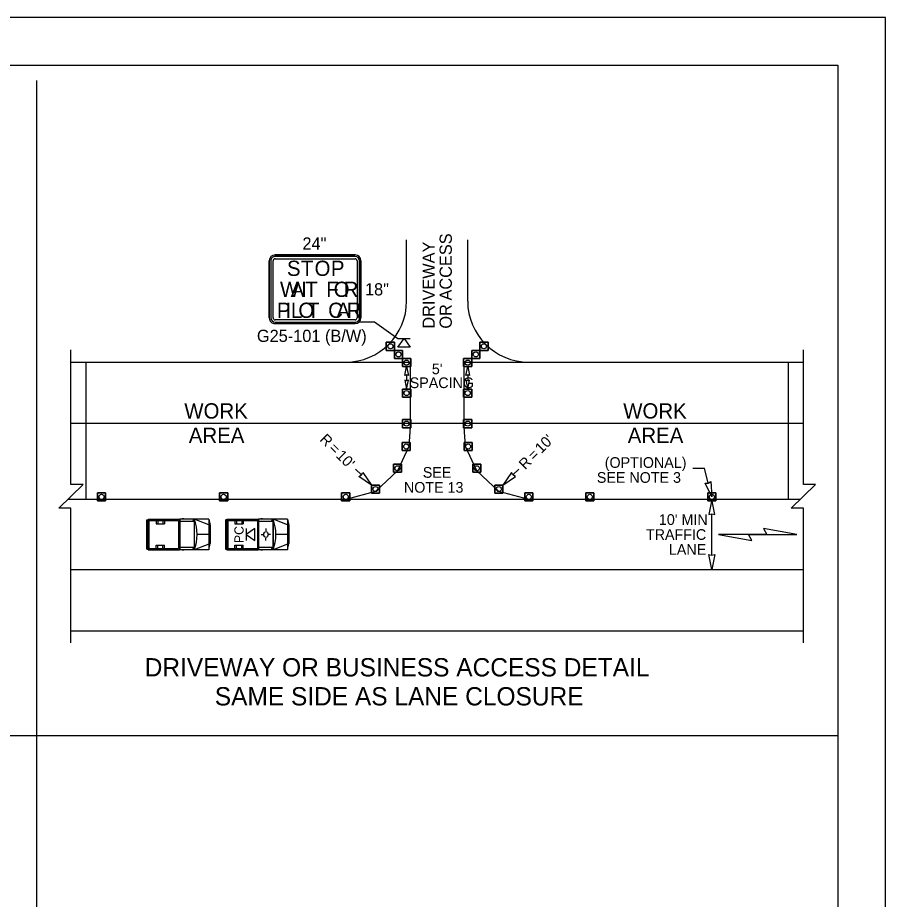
# Model space of a CAD drawing. Extents: x 99999.1 to 100095.7, y 99995 to 100010.7.
# Drawn here: x 100030.38 to 100036.06, y 100004.91 to 100010.69 of the extents above; entities that cross this region are included whole.
import ezdxf

# ---------------------------------------------------------------- set-up
doc = ezdxf.new("R2010")
doc.units = 0
for name, color, linetype in [('RD_ED_DrivewayEdge', 7, 'Continuous'), ('RD_ED_ShoulderPavedEdge', 7, 'Continuous'), ('RD_MK_LineEdgeWhite', 7, 'Continuous'), ('RD_MK_LineSkipCenter', 7, 'Continuous'), ('SH_DE_DetailHeading2Text', 7, 'Continuous'), ('SH_GI_PlotLimits', 7, 'Continuous'), ('SH_GI_SheetBorder', 7, 'Continuous'), ('TR_SN_ConstructionSigns', 7, 'Continuous'), ('TR_WZ_MotoristVehicle', 7, 'Continuous'), ('TR_WZ_PortableSignMountBlk-Wht', 7, 'Continuous'), ('TR_WZ_TrafficCone', 7, 'Continuous'), ('TR_WZ_WorkAreaLabel', 7, 'Continuous'), ('TR_WZ_WorkZoneDetails', 7, 'Continuous'), ('TR_WZ_WorkZoneTextCurrent', 7, 'Continuous')]:
    doc.layers.add(name, color=color, linetype=linetype)

msp = doc.modelspace()

# ---------------------------------------------------------------- linework, layer by layer
at = {"layer": 'RD_ED_DrivewayEdge'}
for p, q in [((100032.925, 100008.8304), (100032.925, 100009.2305)), ((100033.325, 100008.8304), (100033.325, 100009.2305))]:
    msp.add_line(p, q, dxfattribs=at)
for centre, start, end in [((100032.525, 100008.8304), 270, 0), ((100033.725, 100008.8304), 180, 270)]:
    msp.add_arc(centre, 0.4, start, end, dxfattribs=at)
at = {"layer": 'RD_ED_ShoulderPavedEdge'}
for p, q in [((100030.725, 100008.4305), (100032.525, 100008.4305)), ((100033.725, 100008.4305), (100035.525, 100008.4305)), ((100030.725, 100006.6704), (100035.525, 100006.6704))]:
    msp.add_line(p, q, dxfattribs=at)
at = {"layer": 'RD_MK_LineEdgeWhite'}
for p, q in [((100030.725, 100008.0305), (100035.525, 100008.0305)), ((100030.725, 100007.0704), (100035.525, 100007.0704))]:
    msp.add_line(p, q, dxfattribs=at)
at = {"layer": 'RD_MK_LineSkipCenter'}
msp.add_lwpolyline([(100035.5043, 100007.5305), (100030.7043, 100007.5305)], dxfattribs=at)
at = {"layer": 'SH_GI_PlotLimits'}
msp.add_lwpolyline([(100019.0625, 99999.6875), (100036.0625, 99999.6875), (100036.0625, 100010.6875), (100019.0625, 100010.6875)], close=True, dxfattribs=at)
at = {"layer": 'SH_GI_SheetBorder'}
for p, q in [((100020, 100010.375), (100035.75, 100010.375)), ((100035.75, 100010.375), (100035.75, 100000))]:
    msp.add_line(p, q, dxfattribs=at)
at = {"layer": 'TR_SN_ConstructionSigns'}
for p, q in [((100032.025, 100008.7198), (100032.025, 100009.0948)), ((100032.025, 100009.0948), (100032.025, 100008.7198)), ((100032.025, 100009.0948), (100032.025, 100008.7198)), ((100032.0344, 100009.0948), (100032.0344, 100008.7198)), ((100032.05, 100008.7198), (100032.05, 100009.0948)), ((100032.0625, 100009.1323), (100032.5875, 100009.1323)), ((100032.5875, 100009.1323), (100032.0625, 100009.1323)), ((100032.5875, 100009.1323), (100032.0625, 100009.1323)), ((100032.5875, 100009.1229), (100032.0625, 100009.1229)), ((100032.0625, 100009.1073), (100032.5875, 100009.1073)), ((100032.6, 100009.0948), (100032.6, 100008.7198)), ((100032.6156, 100008.7198), (100032.6156, 100009.0948)), ((100032.625, 100009.0948), (100032.625, 100008.7198)), ((100032.625, 100008.7198), (100032.625, 100009.0948)), ((100032.625, 100008.7198), (100032.625, 100009.0948)), ((100032.5875, 100008.7073), (100032.0625, 100008.7073)), ((100032.0625, 100008.6916), (100032.5875, 100008.6916)), ((100032.5875, 100008.6823), (100032.0625, 100008.6823)), ((100032.0625, 100008.6823), (100032.5875, 100008.6823)), ((100032.0625, 100008.6823), (100032.5875, 100008.6823))]:
    msp.add_line(p, q, dxfattribs=at)
for centre, radius, start, end in [((100032.0625, 100009.0948), 0.0375, 90, 180), ((100032.0625, 100009.0948), 0.0375, 90, 180), ((100032.0625, 100009.0948), 0.0375, 90, 180), ((100032.0625, 100009.0948), 0.0281, 90, 180.00001), ((100032.0625, 100009.0948), 0.0125, 90, 180.00001), ((100032.5875, 100009.0948), 0.0375, 0, 90), ((100032.5875, 100009.0948), 0.0375, 0, 90), ((100032.5875, 100009.0948), 0.0375, 0, 90), ((100032.5875, 100009.0948), 0.0281, 0, 90), ((100032.5875, 100009.0948), 0.0125, 0, 90), ((100032.0625, 100008.7198), 0.0375, 180, 270.00001), ((100032.0625, 100008.7198), 0.0375, 180, 270.00001), ((100032.0625, 100008.7198), 0.0375, 180, 270.00001), ((100032.0625, 100008.7198), 0.0281, 180.00001, 270), ((100032.0625, 100008.7198), 0.0125, 180.00001, 270), ((100032.5875, 100008.7198), 0.0375, 270.00001, 0.00001), ((100032.5875, 100008.7198), 0.0375, 270.00001, 0.00001), ((100032.5875, 100008.7198), 0.0281, 270, 0.00001), ((100032.5875, 100008.7198), 0.0125, 270, 0.00001), ((100032.5875, 100008.7198), 0.0375, 270.00001, 0.00001)]:
    msp.add_arc(centre, radius, start, end, dxfattribs=at)
at = {"layer": 'TR_WZ_MotoristVehicle'}
for p, q in [((100031.2207, 100007.3911), (100031.2207, 100007.2098)), ((100031.2252, 100007.3972), (100031.2297, 100007.3972)), ((100031.2297, 100007.3972), (100031.2297, 100007.2037)), ((100031.2304, 100007.4005), (100031.4361, 100007.4005)), ((100031.2304, 100007.4005), (100031.2304, 100007.2005)), ((100031.2362, 100007.3925), (100031.2362, 100007.2084)), ((100031.2362, 100007.3925), (100031.4302, 100007.3925)), ((100031.2826, 100007.3925), (100031.2826, 100007.3695)), ((100031.2826, 100007.3695), (100031.3375, 100007.3695)), ((100031.2936, 100007.3925), (100031.2936, 100007.3695)), ((100031.3276, 100007.3925), (100031.3276, 100007.3695)), ((100031.3375, 100007.3925), (100031.3375, 100007.3695)), ((100031.4302, 100007.3925), (100031.4302, 100007.2084)), ((100031.4361, 100007.4005), (100031.4361, 100007.2005)), ((100031.4388, 100007.4005), (100031.4388, 100007.2005)), ((100031.6277, 100007.4005), (100031.4388, 100007.4005)), ((100031.5316, 100007.385), (100031.4388, 100007.385)), ((100031.4646, 100007.4033), (100031.4533, 100007.4033)), ((100031.5316, 100007.4005), (100031.5195, 100007.385)), ((100031.5316, 100007.4005), (100031.5316, 100007.2005)), ((100031.5333, 100007.4005), (100031.5333, 100007.2005)), ((100031.6277, 100007.3638), (100031.5333, 100007.4005)), ((100031.6277, 100007.4005), (100031.6277, 100007.2005)), ((100031.6277, 100007.4005), (100031.637, 100007.3601)), ((100031.637, 100007.3601), (100031.637, 100007.2408)), ((100031.737, 100007.3911), (100031.737, 100007.2098)), ((100031.7415, 100007.3972), (100031.7459, 100007.3972)), ((100031.7459, 100007.3972), (100031.7459, 100007.2037)), ((100031.7466, 100007.4005), (100031.9523, 100007.4005)), ((100031.7466, 100007.4005), (100031.7466, 100007.2005)), ((100031.7525, 100007.3925), (100031.7525, 100007.2084)), ((100031.7525, 100007.3925), (100031.9465, 100007.3925)), ((100031.7988, 100007.3925), (100031.7988, 100007.3695)), ((100031.7988, 100007.3695), (100031.8538, 100007.3695)), ((100031.8098, 100007.3925), (100031.8098, 100007.3695)), ((100031.8438, 100007.3925), (100031.8438, 100007.3695)), ((100031.8538, 100007.3925), (100031.8538, 100007.3695)), ((100031.9465, 100007.3925), (100031.9465, 100007.2084)), ((100031.9523, 100007.4005), (100031.9523, 100007.2005)), ((100031.9551, 100007.4005), (100031.9551, 100007.2005)), ((100032.144, 100007.4005), (100031.9551, 100007.4005)), ((100032.0478, 100007.385), (100031.9551, 100007.385)), ((100031.9809, 100007.4033), (100031.9695, 100007.4033)), ((100032.0478, 100007.4005), (100032.0358, 100007.385)), ((100032.0478, 100007.4005), (100032.0478, 100007.2005)), ((100032.0495, 100007.4005), (100032.0495, 100007.2005)), ((100032.144, 100007.3638), (100032.0495, 100007.4005)), ((100032.144, 100007.4005), (100032.144, 100007.2005)), ((100032.144, 100007.4005), (100032.1533, 100007.3601)), ((100032.1533, 100007.3601), (100032.1533, 100007.2408)), ((100031.2207, 100007.3145), (100031.2297, 100007.3108)), ((100031.2207, 100007.2864), (100031.2297, 100007.2901)), ((100031.2231, 100007.3005), (100031.2273, 100007.3005)), ((100031.2252, 100007.3033), (100031.2252, 100007.2976)), ((100031.6277, 100007.3005), (100031.5518, 100007.3005)), ((100031.737, 100007.3145), (100031.7459, 100007.3108)), ((100031.737, 100007.2864), (100031.7459, 100007.2901)), ((100031.7394, 100007.3005), (100031.7435, 100007.3005)), ((100031.7415, 100007.3033), (100031.7415, 100007.2976)), ((100031.9716, 100007.2997), (100031.9865, 100007.3001)), ((100031.9884, 100007.3001), (100031.9884, 100007.3001)), ((100032.0025, 100007.3401), (100032.0025, 100007.3239)), ((100032.0326, 100007.3006), (100032.02, 100007.3005)), ((100032.144, 100007.3005), (100032.0681, 100007.3005)), ((100031.6277, 100007.2371), (100031.5333, 100007.2005)), ((100031.6277, 100007.2005), (100031.637, 100007.2408)), ((100032.0018, 100007.262), (100032.0021, 100007.277)), ((100032.144, 100007.2371), (100032.0495, 100007.2005)), ((100032.144, 100007.2005), (100032.1533, 100007.2408)), ((100031.2252, 100007.2037), (100031.2297, 100007.2037)), ((100031.2304, 100007.2005), (100031.4361, 100007.2005)), ((100031.2362, 100007.2084), (100031.4302, 100007.2084)), ((100031.2826, 100007.2084), (100031.2826, 100007.2314)), ((100031.2826, 100007.2314), (100031.3375, 100007.2314)), ((100031.2936, 100007.2084), (100031.2936, 100007.2314)), ((100031.3276, 100007.2084), (100031.3276, 100007.2314)), ((100031.3375, 100007.2084), (100031.3375, 100007.2314)), ((100031.5316, 100007.216), (100031.4388, 100007.216)), ((100031.6277, 100007.2005), (100031.4388, 100007.2005)), ((100031.4646, 100007.1976), (100031.4533, 100007.1976)), ((100031.5216, 100007.216), (100031.5316, 100007.2005)), ((100031.7415, 100007.2037), (100031.7459, 100007.2037)), ((100031.7466, 100007.2005), (100031.9523, 100007.2005)), ((100031.7525, 100007.2084), (100031.9465, 100007.2084)), ((100031.7988, 100007.2084), (100031.7988, 100007.2314)), ((100031.7988, 100007.2314), (100031.8538, 100007.2314)), ((100031.8098, 100007.2084), (100031.8098, 100007.2314)), ((100031.8438, 100007.2084), (100031.8438, 100007.2314)), ((100031.8538, 100007.2084), (100031.8538, 100007.2314)), ((100032.0478, 100007.216), (100031.9551, 100007.216)), ((100032.144, 100007.2005), (100031.9551, 100007.2005)), ((100031.9809, 100007.1976), (100031.9695, 100007.1976)), ((100032.0379, 100007.216), (100032.0478, 100007.2005))]:
    msp.add_line(p, q, dxfattribs=at)
for centre, major_axis, start_param, end_param in [((100031.2252, 100007.3911), (0, 0.0061), 6.283185, 7.853982), ((100031.3983, 100007.3004), (0, 0.2099), 4.215852, 5.209111), ((100031.7415, 100007.3911), (0, 0.0061), 6.283185, 7.853982), ((100031.9146, 100007.3004), (0, 0.2099), 4.215852, 5.209111), ((100031.2252, 100007.2098), (0, -0.0061), 4.712389, 6.283185), ((100031.7415, 100007.2098), (0, -0.0061), 4.712389, 6.283185)]:
    msp.add_ellipse(centre, major_axis=major_axis, ratio=0.73155, start_param=start_param, end_param=end_param, dxfattribs=at)
for centre, major_axis in [((100031.2252, 100007.3005), (0, -0.00282)), ((100031.7415, 100007.3005), (0, -0.00282)), ((100032.0025, 100007.3005), (0, -0.0193))]:
    msp.add_ellipse(centre, major_axis=major_axis, ratio=0.73155, dxfattribs=at)
at = {"layer": 'TR_WZ_PortableSignMountBlk-Wht'}
for p, q in [((100032.8683, 100008.5846), (100032.9483, 100008.5846)), ((100031.8727, 100007.3404), (100031.8727, 100007.2604))]:
    msp.add_line(p, q, dxfattribs=at)
for points in [[(100032.9083, 100008.5846), (100032.9483, 100008.5271), (100032.8683, 100008.5271)], [(100031.8727, 100007.3004), (100031.9301, 100007.2604), (100031.9301, 100007.3404)]]:
    msp.add_lwpolyline(points, close=True, dxfattribs=at)
at = {"layer": 'TR_WZ_TrafficCone'}
for points in [[(100032.7917, 100008.5605), (100032.845, 100008.5605), (100032.845, 100008.5071), (100032.7917, 100008.5071), (100032.7917, 100008.5605)], [(100032.7917, 100008.5071), (100032.845, 100008.5071), (100032.845, 100008.5605), (100032.7917, 100008.5605), (100032.7917, 100008.5071)], [(100033.405, 100008.5605), (100033.4583, 100008.5605), (100033.4583, 100008.5071), (100033.405, 100008.5071), (100033.405, 100008.5605)], [(100033.405, 100008.5071), (100033.4583, 100008.5071), (100033.4583, 100008.5605), (100033.405, 100008.5605), (100033.405, 100008.5071)], [(100032.845, 100008.5071), (100032.8984, 100008.5071), (100032.8984, 100008.4538), (100032.845, 100008.4538), (100032.845, 100008.5071)], [(100032.845, 100008.4538), (100032.8984, 100008.4538), (100032.8984, 100008.5071), (100032.845, 100008.5071), (100032.845, 100008.4538)], [(100033.3516, 100008.5071), (100033.405, 100008.5071), (100033.405, 100008.4538), (100033.3516, 100008.4538), (100033.3516, 100008.5071)], [(100033.3516, 100008.4538), (100033.405, 100008.4538), (100033.405, 100008.5071), (100033.3516, 100008.5071), (100033.3516, 100008.4538)], [(100032.8984, 100008.4538), (100032.9517, 100008.4538), (100032.9517, 100008.4005), (100032.8984, 100008.4005), (100032.8984, 100008.4538)], [(100032.8984, 100008.4005), (100032.9517, 100008.4005), (100032.9517, 100008.4538), (100032.8984, 100008.4538), (100032.8984, 100008.4005)], [(100033.2983, 100008.4538), (100033.3516, 100008.4538), (100033.3516, 100008.4005), (100033.2983, 100008.4005), (100033.2983, 100008.4538)], [(100033.2983, 100008.4005), (100033.3516, 100008.4005), (100033.3516, 100008.4538), (100033.2983, 100008.4538), (100033.2983, 100008.4005)], [(100032.8984, 100008.2538), (100032.9517, 100008.2538), (100032.9517, 100008.2005), (100032.8984, 100008.2005), (100032.8984, 100008.2538)], [(100032.8984, 100008.2005), (100032.9517, 100008.2005), (100032.9517, 100008.2538), (100032.8984, 100008.2538), (100032.8984, 100008.2005)], [(100033.2983, 100008.2538), (100033.3516, 100008.2538), (100033.3516, 100008.2005), (100033.2983, 100008.2005), (100033.2983, 100008.2538)], [(100033.2983, 100008.2005), (100033.3516, 100008.2005), (100033.3516, 100008.2538), (100033.2983, 100008.2538), (100033.2983, 100008.2005)], [(100032.8984, 100008.0538), (100032.9517, 100008.0538), (100032.9517, 100008.0005), (100032.8984, 100008.0005), (100032.8984, 100008.0538)], [(100032.8984, 100008.0005), (100032.9517, 100008.0005), (100032.9517, 100008.0538), (100032.8984, 100008.0538), (100032.8984, 100008.0005)], [(100033.2983, 100008.0538), (100033.3516, 100008.0538), (100033.3516, 100008.0005), (100033.2983, 100008.0005), (100033.2983, 100008.0538)], [(100033.2983, 100008.0005), (100033.3516, 100008.0005), (100033.3516, 100008.0538), (100033.2983, 100008.0538), (100033.2983, 100008.0005)], [(100032.8956, 100007.9038), (100032.949, 100007.9038), (100032.949, 100007.8505), (100032.8956, 100007.8505), (100032.8956, 100007.9038)], [(100032.8956, 100007.8505), (100032.949, 100007.8505), (100032.949, 100007.9038), (100032.8956, 100007.9038), (100032.8956, 100007.8505)], [(100033.301, 100007.9038), (100033.3544, 100007.9038), (100033.3544, 100007.8505), (100033.301, 100007.8505), (100033.301, 100007.9038)], [(100033.301, 100007.8505), (100033.3544, 100007.8505), (100033.3544, 100007.9038), (100033.301, 100007.9038), (100033.301, 100007.8505)], [(100032.8381, 100007.7615), (100032.8914, 100007.7615), (100032.8914, 100007.7082), (100032.8381, 100007.7082), (100032.8381, 100007.7615)], [(100032.8381, 100007.7082), (100032.8914, 100007.7082), (100032.8914, 100007.7615), (100032.8381, 100007.7615), (100032.8381, 100007.7082)], [(100033.3586, 100007.7615), (100033.4119, 100007.7615), (100033.4119, 100007.7082), (100033.3586, 100007.7082), (100033.3586, 100007.7615)], [(100033.3586, 100007.7082), (100033.4119, 100007.7082), (100033.4119, 100007.7615), (100033.3586, 100007.7615), (100033.3586, 100007.7082)], [(100032.6944, 100007.6247), (100032.7477, 100007.6247), (100032.7477, 100007.5714), (100032.6944, 100007.5714), (100032.6944, 100007.6247)], [(100032.6944, 100007.5714), (100032.7477, 100007.5714), (100032.7477, 100007.6247), (100032.6944, 100007.6247), (100032.6944, 100007.5714)], [(100033.5023, 100007.6247), (100033.5556, 100007.6247), (100033.5556, 100007.5714), (100033.5023, 100007.5714), (100033.5023, 100007.6247)], [(100033.5023, 100007.5714), (100033.5556, 100007.5714), (100033.5556, 100007.6247), (100033.5023, 100007.6247), (100033.5023, 100007.5714)], [(100030.899, 100007.5738), (100030.9524, 100007.5738), (100030.9524, 100007.5205), (100030.899, 100007.5205), (100030.899, 100007.5738)], [(100030.899, 100007.5205), (100030.9524, 100007.5205), (100030.9524, 100007.5738), (100030.899, 100007.5738), (100030.899, 100007.5205)], [(100031.699, 100007.5738), (100031.7524, 100007.5738), (100031.7524, 100007.5205), (100031.699, 100007.5205), (100031.699, 100007.5738)], [(100031.699, 100007.5205), (100031.7524, 100007.5205), (100031.7524, 100007.5738), (100031.699, 100007.5738), (100031.699, 100007.5205)], [(100032.499, 100007.5738), (100032.5524, 100007.5738), (100032.5524, 100007.5205), (100032.499, 100007.5205), (100032.499, 100007.5738)], [(100032.499, 100007.5205), (100032.5524, 100007.5205), (100032.5524, 100007.5738), (100032.499, 100007.5738), (100032.499, 100007.5205)], [(100033.699, 100007.5738), (100033.7524, 100007.5738), (100033.7524, 100007.5205), (100033.699, 100007.5205), (100033.699, 100007.5738)], [(100033.699, 100007.5205), (100033.7524, 100007.5205), (100033.7524, 100007.5738), (100033.699, 100007.5738), (100033.699, 100007.5205)], [(100034.099, 100007.5738), (100034.1524, 100007.5738), (100034.1524, 100007.5205), (100034.099, 100007.5205), (100034.099, 100007.5738)], [(100034.099, 100007.5205), (100034.1524, 100007.5205), (100034.1524, 100007.5738), (100034.099, 100007.5738), (100034.099, 100007.5205)], [(100034.899, 100007.5738), (100034.9524, 100007.5738), (100034.9524, 100007.5205), (100034.899, 100007.5205), (100034.899, 100007.5738)], [(100034.899, 100007.5205), (100034.9524, 100007.5205), (100034.9524, 100007.5738), (100034.899, 100007.5738), (100034.899, 100007.5205)]]:
    msp.add_lwpolyline(points, dxfattribs=at)
for centre in [(100032.8184, 100008.5338), (100033.4316, 100008.5338), (100032.8717, 100008.4805), (100033.3783, 100008.4805), (100032.925, 100008.4271), (100033.325, 100008.4271), (100032.925, 100008.2271), (100033.325, 100008.2271), (100032.925, 100008.0271), (100033.325, 100008.0271), (100032.9223, 100007.8771), (100033.3277, 100007.8771), (100032.8648, 100007.7349), (100033.3852, 100007.7349), (100032.721, 100007.598), (100033.529, 100007.598), (100030.9257, 100007.5471), (100031.7257, 100007.5471), (100032.5257, 100007.5471), (100033.7257, 100007.5471), (100034.1257, 100007.5471), (100034.9257, 100007.5471)]:
    msp.add_circle(centre, 0.0167, dxfattribs=at)
at = {"layer": 'TR_WZ_WorkZoneDetails'}
for p, q in [((100030.5, 100010.275), (100030.5, 100001.6859)), ((100032.614, 100008.6933), (100032.714, 100008.6933)), ((100032.714, 100008.6933), (100032.8683, 100008.5846)), ((100032.9251, 100008.3459), (100032.9251, 100008.3083)), ((100033.325, 100008.3459), (100033.325, 100008.3083)), ((100032.6281, 100007.691), (100032.5897, 100007.7294)), ((100033.6219, 100007.691), (100033.6603, 100007.7294)), ((100034.8007, 100007.7352), (100034.8769, 100007.7352)), ((100034.9022, 100007.6378), (100034.8769, 100007.7352)), ((100034.9256, 100007.1642), (100034.9256, 100007.4367)), ((100035.2856, 100007.3005), (100035.0445, 100007.3005)), ((100035.1651, 100007.3005), (100035.4062, 100007.3005)), ((100030.5, 100005.9804), (100025.25, 100005.9804)), ((100035.75, 100005.9804), (100030.5, 100005.9804))]:
    msp.add_line(p, q, dxfattribs=at)
for points in [[(100030.725, 100006.5904), (100030.725, 100007.473), (100030.645, 100007.473), (100030.805, 100007.6279), (100030.725, 100007.6279), (100030.725, 100008.5105)], [(100035.525, 100006.5904), (100035.525, 100007.473), (100035.445, 100007.473), (100035.605, 100007.6279), (100035.525, 100007.6279), (100035.525, 100008.5105)]]:
    msp.add_lwpolyline(points, dxfattribs=at)
for points in [[(100032.9483, 100008.4305), (100032.9483, 100008.2071), (100032.9483, 100008.0071), (100032.939, 100007.8771), (100032.939, 100007.8771), (100032.939, 100007.8771), (100032.8648, 100007.7182), (100032.8648, 100007.7182), (100032.8648, 100007.7182), (100032.721, 100007.5814), (100032.5257, 100007.5305), (100031.529, 100007.5305), (100030.949, 100007.5305), (100030.825, 100007.5305), (100030.825, 100008.4305)], [(100032.925, 100008.4005), (100032.9363, 100008.3433), (100032.925, 100008.3459), (100032.9138, 100008.3433)], [(100035.425, 100008.4305), (100035.425, 100008.0305), (100035.425, 100007.5305), (100034.501, 100007.5305), (100034.501, 100007.5305), (100034.501, 100007.5305), (100033.7257, 100007.5305), (100033.7257, 100007.5305), (100033.7257, 100007.5305), (100033.529, 100007.5814), (100033.3852, 100007.7182), (100033.311, 100007.8771), (100033.3017, 100008.0071), (100033.3017, 100008.2071), (100033.3017, 100008.4305)], [(100033.325, 100008.4005), (100033.3362, 100008.3433), (100033.325, 100008.3459), (100033.3137, 100008.3433)], [(100032.9251, 100008.2538), (100032.9363, 100008.3109), (100032.9251, 100008.3083), (100032.9139, 100008.3109)], [(100033.325, 100008.2538), (100033.3362, 100008.3109), (100033.325, 100008.3083), (100033.3138, 100008.3109)], [(100032.6944, 100007.6247), (100032.6113, 100007.6806), (100032.6281, 100007.691), (100032.6385, 100007.7079)], [(100033.5556, 100007.6247), (100033.6387, 100007.6806), (100033.6219, 100007.691), (100033.6115, 100007.7079)], [(100034.9257, 100007.5471), (100034.8824, 100007.6374), (100034.9022, 100007.6379), (100034.9197, 100007.6471)], [(100034.9257, 100007.5305), (100034.9064, 100007.4322), (100034.9257, 100007.4367), (100034.945, 100007.4322)], [(100034.9685, 100007.3005), (100035.1873, 100007.2619), (100035.1651, 100007.3005)], [(100035.4821, 100007.3005), (100035.2633, 100007.339), (100035.2856, 100007.3005)], [(100034.9256, 100007.0704), (100034.9064, 100007.1687), (100034.9256, 100007.1642), (100034.9449, 100007.1687)]]:
    msp.add_lwpolyline(points, close=True, dxfattribs=at)

# ---------------------------------------------------------------- texts
at = {"layer": 'SH_DE_DetailHeading2Text'}
for s, p in [('DRIVEWAY OR BUSINESS ACCESS DETAIL', (100031.2082, 100006.3704)), ('SAME SIDE AS LANE CLOSURE', (100031.6677, 100006.1804))]:
    msp.add_text(s, height=0.12, rotation=360, dxfattribs=at).set_placement(p)
at = {"layer": 'TR_SN_ConstructionSigns'}
for s, p in [('24"', (100032.2419, 100009.1673)), ('18"', (100032.6519, 100008.8673)), ('G25-101 (B/W)', (100031.9438, 100008.5623))]:
    msp.add_text(s, height=0.08, rotation=360, dxfattribs=at).set_placement(p)
for s, p in [('S', (100032.1405, 100008.9948)), ('T', (100032.2325, 100008.9948)), ('O', (100032.3215, 100008.9948)), ('P', (100032.4285, 100008.9948)), ('W', (100032.095, 100008.8573)), ('A', (100032.165, 100008.8573)), ('I', (100032.233, 100008.8573)), ('T', (100032.26, 100008.8573)), ('F', (100032.398, 100008.8573)), ('O', (100032.447, 100008.8573)), ('R', (100032.512, 100008.8573)), ('P', (100032.0745, 100008.7198)), ('I', (100032.1315, 100008.7198)), ('L', (100032.1665, 100008.7198)), ('O', (100032.2155, 100008.7198)), ('T', (100032.2725, 100008.7198)), ('C', (100032.4105, 100008.7198)), ('A', (100032.4645, 100008.7198)), ('R', (100032.5325, 100008.7198))]:
    msp.add_text(s, height=0.1, dxfattribs=at).set_placement(p)
at = {"layer": 'TR_WZ_MotoristVehicle'}
msp.add_text('PC', height=0.06, rotation=90, dxfattribs=at).set_placement((100031.8563, 100007.2444))
at = {"layer": 'TR_WZ_WorkAreaLabel'}
for s, p in [('WORK', (100031.4678, 100008.0605)), ('WORK', (100034.3444, 100008.0605)), ('AREA', (100031.4974, 100007.9004)), ('AREA', (100034.3741, 100007.9004))]:
    msp.add_text(s, height=0.1, dxfattribs=at).set_placement(p)
at = {"layer": 'TR_WZ_WorkZoneTextCurrent'}
for s, height, rotation, p in [('ACCESS', 0.08, 90, (100033.221, 100008.8338)), ('DRIVEWAY', 0.08, 90, (100033.109, 100008.6495)), ('OR', 0.08, 90, (100033.221, 100008.6495)), ('R', 0.07, 315, (100032.3509, 100007.9186)), ("10'", 0.07, 45, (100033.8075, 100007.8271)), ('=', 0.07, 315, (100032.4101, 100007.8595)), ("10'", 0.07, 315, (100032.457, 100007.8126)), ('=', 0.07, 45, (100033.7606, 100007.7802)), ('R', 0.07, 45, (100033.7015, 100007.7211))]:
    msp.add_text(s, height=height, rotation=rotation, dxfattribs=at).set_placement(p)
for s, p in [("5'", (100033.0904, 100008.3509)), ('SPACING', (100032.945, 100008.2599)), ('(OPTIONAL)', (100034.2233, 100007.7372)), ('SEE', (100033.0308, 100007.6725)), ('SEE NOTE 3', (100034.1716, 100007.6392)), ('NOTE 13', (100032.9072, 100007.5745)), ("10' MIN", (100034.5783, 100007.3635)), ('TRAFFIC', (100034.4933, 100007.2655)), ('LANE', (100034.6437, 100007.1675))]:
    msp.add_text(s, height=0.07, dxfattribs=at).set_placement(p)

doc.saveas('drawing.dxf')
